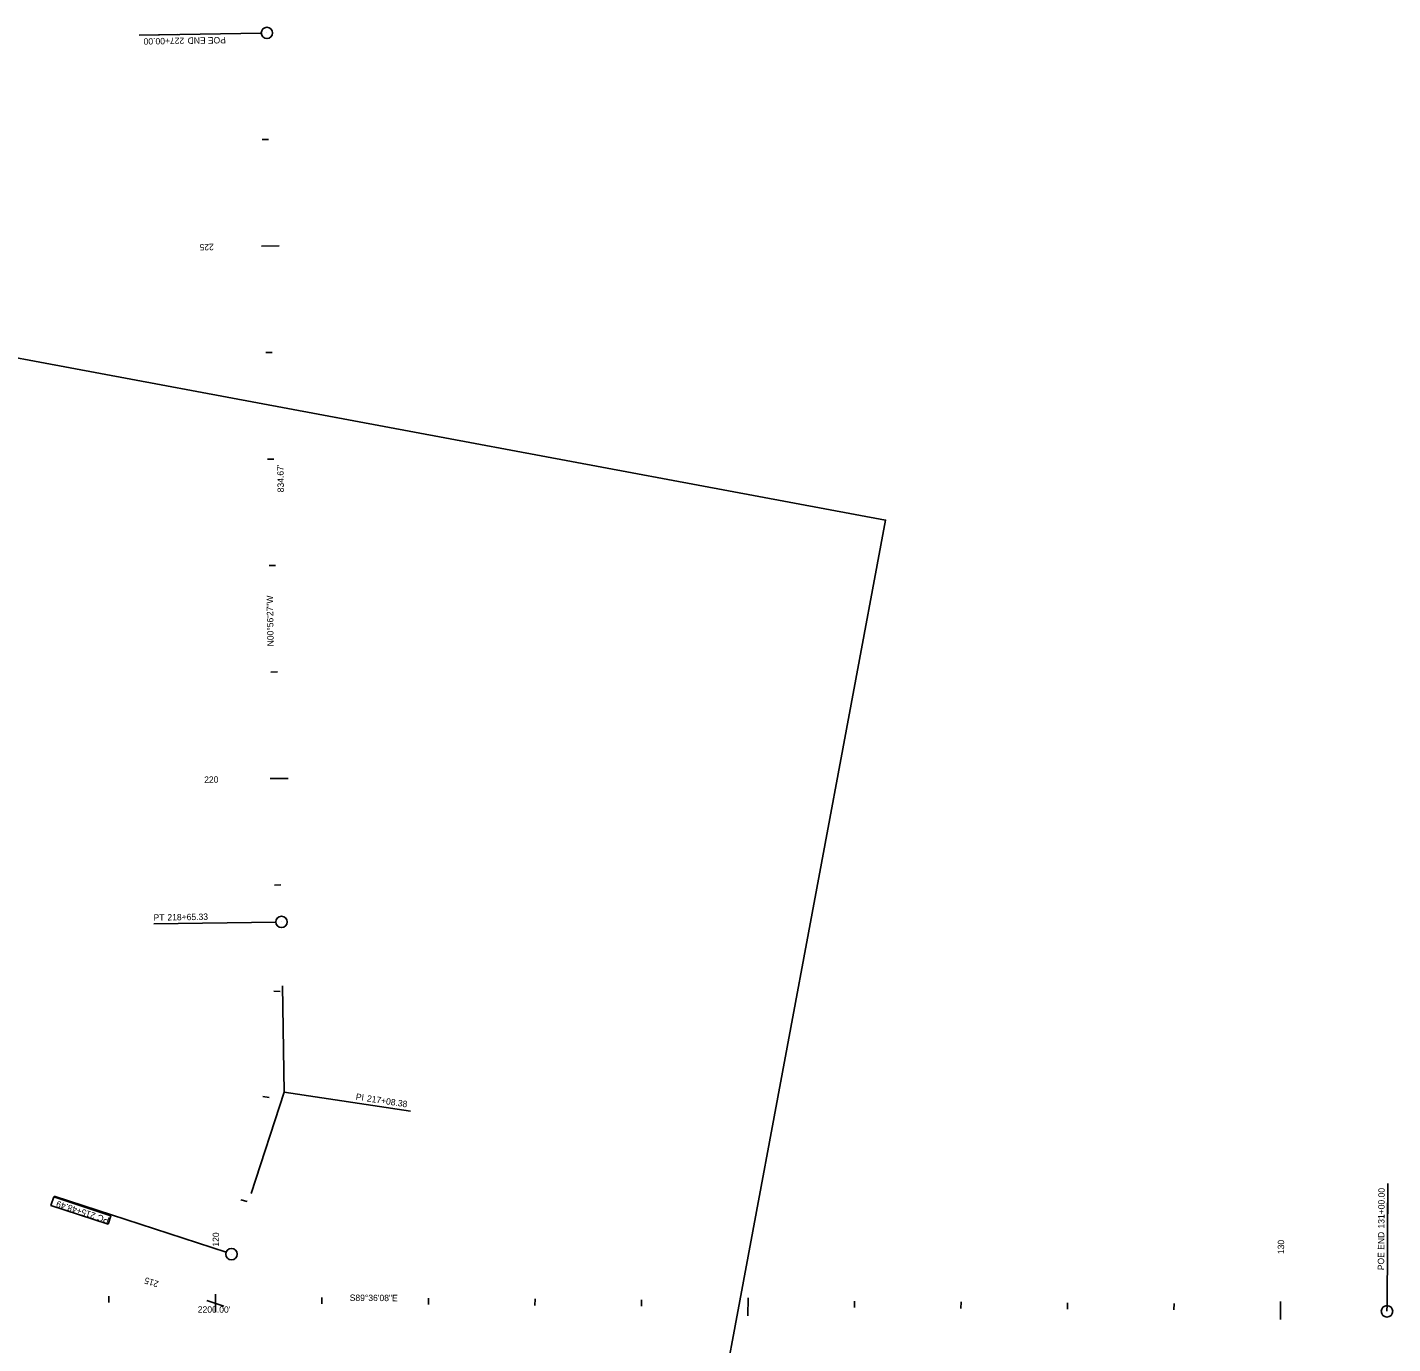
# Model space of a CAD drawing. Extents: x 1802363 to 1804577, y 570221 to 575010.
# Drawn here: x 1803296 to 1804577, y 573774 to 575010 of the extents above; entities that cross this region are included whole.
import ezdxf

# ---------------------------------------------------------------- set-up
doc = ezdxf.new("R2010")
doc.units = 0
for name, color, linetype in [('Default', 7, 'Continuous'), ('S_CROSS_DRAIN', 7, 'Continuous'), ('S_FENCE', 7, 'Continuous'), ('S_SIGN', 7, 'Continuous')]:
    doc.layers.add(name, color=color, linetype=linetype)

msp = doc.modelspace()

# ---------------------------------------------------------------- linework, layer by layer
at = {"layer": 'Default'}
msp.add_lwpolyline([(1803371.3, 573886.5), (1803374, 573894.5), (1803320.3, 573912.1), (1803317.7, 573904.1)], close=True, dxfattribs=at)
at = {"layer": 'S_CROSS_DRAIN'}
for p, q in [((1803515.1, 575004.8), (1803400.5, 575002.9)), ((1803400.5, 575002.9), (1803436.5, 575003.5)), ((1803520.5, 575004.9), (1803520.5, 575004.9)), ((1803516.1, 574904.8), (1803522.1, 574904.9)), ((1803515.3, 574804.8), (1803532.1, 574805)), ((1803519.4, 574704.8), (1803525.4, 574704.9)), ((1803521, 574604.8), (1803527, 574604.9)), ((1803522.7, 574504.8), (1803528.7, 574504.9)), ((1803524.3, 574404.9), (1803530.3, 574405)), ((1803523.5, 574304.8), (1803540.3, 574305.1)), ((1803527.6, 574204.9), (1803533.6, 574205)), ((1803528.8, 574170.2), (1803414.2, 574168.4)), ((1803414.2, 574168.4), (1803414.2, 574168.4)), ((1803534.2, 574170.3), (1803534.2, 574170.3)), ((1803527, 574105.3), (1803533, 574105)), ((1803536.8, 574010.5), (1803535.1, 574110.4)), ((1803536.8, 574010.5), (1803505.8, 573915.4)), ((1803516.7, 574006.5), (1803522.6, 574005.6)), ((1803536.8, 574010.5), (1803655.4, 573992.6)), ((1803655.4, 573992.6), (1803655.4, 573992.6)), ((1804572.2, 573810), (1804573, 573924.7)), ((1804573, 573924.7), (1804572.7, 573888.7)), ((1803482.1, 573860.1), (1803320.8, 573912.7)), ((1803496, 573909.4), (1803501.8, 573907.8)), ((1803373.1, 573895.7), (1803373.1, 573895.7)), ((1803487.2, 573858.4), (1803487.2, 573858.4)), ((1803472.2, 573820.7), (1803472.1, 573803.9)), ((1803372.2, 573819), (1803372.2, 573813)), ((1803464.2, 573815), (1803480.1, 573809.7)), ((1803572.2, 573817.7), (1803572.1, 573811.7)), ((1803672.2, 573817), (1803672.1, 573811)), ((1803772.2, 573816.3), (1803772.1, 573810.3)), ((1803872.2, 573815.6), (1803872.1, 573809.6)), ((1803972.2, 573817.3), (1803972.1, 573800.5)), ((1804072.2, 573814.2), (1804072.1, 573808.2)), ((1804172.2, 573813.5), (1804172.1, 573807.5)), ((1804272.2, 573812.8), (1804272.1, 573806.8)), ((1804372.2, 573812.1), (1804372.1, 573806.1)), ((1804472.2, 573813.8), (1804472.1, 573797)), ((1804572.2, 573810.7), (1804572.1, 573804.7)), ((1804572.1, 573804.7), (1804572.1, 573804.7))]:
    msp.add_line(p, q, dxfattribs=at)
for centre in [(1803520.5, 575004.9), (1803534.2, 574170.3), (1803487.2, 573858.4), (1804572.1, 573804.7)]:
    msp.add_circle(centre, 5.34, dxfattribs=at)
at = {"layer": 'S_SIGN'}
msp.add_lwpolyline([(1802779, 573185.2), (1803811.2, 572992.6), (1804101.3, 574547.6), (1803069.1, 574740.2)], close=True, dxfattribs=at)

# ---------------------------------------------------------------- texts
at = {"layer": 'S_CROSS_DRAIN'}
for s, rotation, p in [('227+00.00', 180.9408, (1803442.8, 575000.6)), ('END', 180.9408, (1803462.9, 575000.9)), ('POE ', 180.9408, (1803481.9, 575001.2)), ('225', 180.9408, (1803470.6, 574807)), ('N00°56\'27"W', 90.9408, (1803526.9, 574429.1)), ('220', 0.9408, (1803461.6, 574300.8)), ('PT', 0.9408, (1803414.1, 574171.4)), ('218+65.33', 0.9408, (1803427.1, 574171.6)), ('PI ', 351.4356, (1803603.6, 574003.4)), ('217+08.38', 351.4356, (1803614.1, 574001.8)), ('131+00.00', 89.6021, (1804569.7, 573882.4)), ('215+48.49', 161.9303, (1803360.1, 573896.8)), ('PC', 161.9303, (1803373, 573892.5)), ('120', 89.6021, (1803475.5, 573865.4)), ('130', 89.6021, (1804475.5, 573858.4)), ('END', 89.6021, (1804569.5, 573862.4)), ('POE ', 89.6021, (1804569.4, 573843.3)), ('215', 161.9303, (1803419.4, 573832.7)), ('S89°36\'08"E', 359.6021, (1803598.2, 573814.5))]:
    msp.add_text(s, height=6, rotation=rotation, dxfattribs=at).set_placement(p)
at = {"layer": 'S_FENCE'}
for s, rotation, p in [("834.67'", 90.9408, (1803536.5, 574573.7)), ("2200.00'", 359.6021, (1803455.6, 573803.5))]:
    msp.add_text(s, height=6, rotation=rotation, dxfattribs=at).set_placement(p)

doc.saveas('drawing.dxf')
